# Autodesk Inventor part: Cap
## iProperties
Created: 2002-02
Part Number: Cap
Document SubType Name: Modeling
Designer: ***
Control State: 0
Master: False
Checked Out: False
Shininess: 77.0
Length Units: 11269
Angle Units: 11279
Time Units: 11290
Mass Units: 11283
Length Display Precision: 3
Angle Display Precision: 2
Density: 0.0
Volumn: 0.0
Area: 0.0
PropertySet Name: Model Information
Author: ***
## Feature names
1. Extrusion1
2. Extrusion2
3. Hole1
4. Hole2
5. Mirror1
6. Hole3
